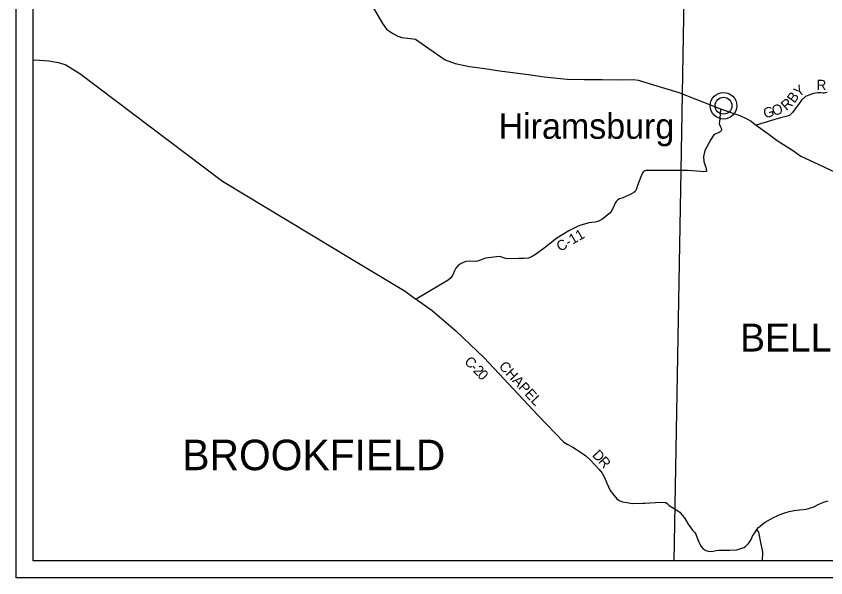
# Model space of a CAD drawing. Extents: x -452339 to 6403467, y -1 to 1814750.
# Drawn here: x -403540 to -379658, y 1603479 to 1620054 of the extents above; entities that cross this region are included whole.
import ezdxf

# ---------------------------------------------------------------- set-up
doc = ezdxf.new("R2010")
doc.units = 0
for name, color, linetype in [('Default', 7, 'Continuous'), ('GM_X_Adjacent_County_Text', 7, 'Continuous'), ('GM_X_County', 7, 'Continuous'), ('GM_X_County_Road', 7, 'Continuous'), ('GM_X_County_Road_Text', 7, 'Continuous'), ('GM_X_Section_Text', 7, 'Continuous'), ('GM_X_Township_Subdivision_Text', 7, 'Continuous')]:
    doc.layers.add(name, color=color, linetype=linetype)

msp = doc.modelspace()

# ---------------------------------------------------------------- linework, layer by layer
at = {"layer": 'Default'}
for p, q in [((-403040, 1603979), (-403040, 1661357)), ((-345663, 1603979), (-403040, 1603979))]:
    msp.add_line(p, q, dxfattribs=at)
msp.add_lwpolyline([(-403540, 1661857), (-345163, 1661857), (-345163, 1603479), (-403540, 1603479)], close=True, dxfattribs=at)
for points in [[(-403040, 1618761), (-402986, 1618762), (-402578, 1618733), (-402288, 1618691), (-402080, 1618619), (-401660, 1618363), (-397451, 1615188), (-393644, 1612887), (-392067, 1611935), (-391791, 1611737)], [(-379622, 1617798), (-379662, 1617791), (-379702, 1617783), (-379740, 1617784), (-379800, 1617793), (-379892, 1617795), (-380024, 1617775), (-380157, 1617728), (-380256, 1617681), (-380370, 1617576), (-380443, 1617481), (-380636, 1617211), (-380685, 1617158), (-380733, 1617127), (-380834, 1617093), (-380991, 1617054), (-381157, 1617007), (-381715, 1616841)], [(-382760, 1617316), (-382786, 1617034), (-382798, 1616944), (-382800, 1616892), (-382798, 1616861), (-382776, 1616813), (-382742, 1616749), (-382732, 1616703), (-382742, 1616675), (-382770, 1616643), (-382834, 1616607), (-382924, 1616573), (-382956, 1616555), (-382982, 1616525), (-383052, 1616412), (-383231, 1616087), (-383261, 1615913), (-383259, 1615770), (-383187, 1615558), (-383181, 1615475), (-383265, 1615460), (-383348, 1615469), (-383717, 1615497), (-384007, 1615505), (-384028, 1615504)], [(-384028, 1615504), (-384672, 1615496), (-384952, 1615500), (-384994, 1615490), (-385034, 1615466), (-385064, 1615428), (-385110, 1615311), (-385214, 1615055), (-385242, 1614961), (-385283, 1614884), (-385319, 1614846), (-385393, 1614816), (-385599, 1614718), (-385675, 1614687), (-385741, 1614661), (-385789, 1614631), (-385837, 1614587), (-385871, 1614535), (-385929, 1614397), (-385993, 1614292), (-386033, 1614242), (-386103, 1614178), (-386190, 1614110), (-386266, 1614056), (-386384, 1613997), (-386460, 1613971), (-386558, 1613961), (-386646, 1613953), (-386712, 1613937), (-386884, 1613888), (-386962, 1613860), (-387242, 1613722), (-387588, 1613501), (-387967, 1613206), (-388195, 1613037), (-388319, 1612961), (-388431, 1612913), (-388557, 1612901), (-388709, 1612900), (-389058, 1612890), (-389134, 1612910), (-389214, 1612946), (-389276, 1612960), (-389372, 1612949), (-389684, 1612913), (-389756, 1612893), (-389846, 1612857), (-389928, 1612826), (-390002, 1612814), (-390170, 1612820), (-390280, 1612814), (-390410, 1612758), (-390500, 1612695), (-390568, 1612617), (-390612, 1612539), (-390661, 1612423), (-390717, 1612337), (-390797, 1612266), (-391746, 1611704)], [(-391791, 1611737), (-391791, 1611737), (-391746, 1611704), (-391272, 1611365), (-390567, 1610765), (-389732, 1609970), (-388143, 1608271), (-387381, 1607484), (-387267, 1607410), (-387119, 1607336), (-387008, 1607266), (-386868, 1607170), (-386738, 1607080), (-386598, 1606956), (-386342, 1606678), (-386258, 1606564), (-386188, 1606436), (-386116, 1606270), (-386016, 1606054), (-385912, 1605920), (-385818, 1605814), (-385750, 1605760), (-385656, 1605718), (-385524, 1605700), (-385356, 1605674), (-385060, 1605679), (-385000, 1605682)], [(-385000, 1605682), (-384520, 1605708), (-384404, 1605706), (-384377, 1605704), (-384338, 1605674), (-384335, 1605671)], [(-384335, 1605671), (-384331, 1605667), (-384286, 1605620), (-384244, 1605597), (-384134, 1605524), (-383961, 1605414), (-383891, 1605329), (-383828, 1605252), (-383718, 1605066), (-383588, 1604888), (-383522, 1604818), (-383506, 1604784), (-383416, 1604560), (-383343, 1604410), (-383287, 1604342), (-383197, 1604288), (-383125, 1604264), (-383063, 1604258), (-382977, 1604268), (-382896, 1604287), (-382810, 1604297), (-382486, 1604299), (-382278, 1604305), (-382076, 1604374), (-382022, 1604404), (-381936, 1604488), (-381864, 1604608), (-381820, 1604707), (-381754, 1604811), (-381690, 1604909)], [(-381690, 1604909), (-381640, 1604967), (-381517, 1605069), (-381447, 1605122), (-381201, 1605260), (-381073, 1605322), (-380959, 1605367), (-380869, 1605401), (-380741, 1605437), (-380593, 1605465), (-380513, 1605473), (-380235, 1605510), (-380139, 1605530), (-380014, 1605572), (-379860, 1605649), (-379766, 1605695), (-379722, 1605711), (-379586, 1605749)], [(-381521, 1603979), (-381516, 1604223), (-381524, 1604291), (-381560, 1604475), (-381638, 1604829), (-381658, 1604867), (-381690, 1604909)]]:
    msp.add_lwpolyline(points, dxfattribs=at)
at = {"layer": 'GM_X_County_Road'}
msp.add_lwpolyline([(-393477, 1621106), (-392730, 1619837), (-392615, 1619675), (-392530, 1619609), (-392432, 1619547), (-392265, 1619452), (-392247, 1619451), (-392165, 1619427), (-391992, 1619405), (-391764, 1619379), (-391371, 1619098), (-390890, 1618764), (-390593, 1618659), (-390170, 1618573), (-389719, 1618515), (-389280, 1618443), (-388428, 1618336), (-387965, 1618264), (-387286, 1618195), (-386781, 1618186), (-386250, 1618188), (-385687, 1618179), (-385330, 1618183), (-385186, 1618167), (-385062, 1618130), (-383990, 1617804), (-382760, 1617316), (-382398, 1617192), (-382197, 1617125), (-382008, 1617034), (-381858, 1616954), (-381737, 1616856), (-381715, 1616841), (-381366, 1616595), (-381090, 1616386), (-380614, 1616078), (-380391, 1615926), (-379863, 1615680), (-379083, 1615313)], dxfattribs=at)
at = {"layer": 'GM_X_County_Road_Text'}
for radius in [393, 249]:
    msp.add_circle((-382675, 1617412), radius, dxfattribs=at)
at = {"layer": 'GM_X_Section_Text'}
for p, q in [((-383695, 1628810), (-383932, 1615503)), ((-383932, 1615503), (-384137, 1603979))]:
    msp.add_line(p, q, dxfattribs=at)

# ---------------------------------------------------------------- texts
at = {"layer": 'GM_X_Adjacent_County_Text'}
for s, height, p in [('Hiramsburg', 750, (-389311, 1616436)), ('BELLE VALLEY', 823.68, (-382185, 1610157))]:
    msp.add_text(s, height=height, rotation=0, dxfattribs=at).set_placement(p)
at = {"layer": 'GM_X_County'}
for s, rotation, p in [('Y', 37.7945, (-380456, 1617651)), ('R', 0.1836, (-379932, 1617876)), ('B', 54.1603, (-380585, 1617467)), ('R', 41.3104, (-380819, 1617250)), ('G', 15.9564, (-381453, 1617036)), ('O', 16.0094, (-381199, 1617109)), ('C-11', 30.0336, (-387496, 1613097)), ('C', 315.8418, (-390342, 1609833)), ('-', 314.9117, (-390167, 1609662)), ('2', 314.2567, (-390080, 1609576)), ('CHAPEL', 312.9989, (-389320, 1609705)), ('0', 313.7672, (-389952, 1609444)), ('D', 313.0162, (-386566, 1607087)), ('R', 312.2225, (-386387, 1606895))]:
    msp.add_text(s, height=300, rotation=rotation, dxfattribs=at).set_placement(p)
at = {"layer": 'GM_X_Township_Subdivision_Text'}
msp.add_text('BROOKFIELD', height=900, rotation=0, dxfattribs=at).set_placement((-398640, 1606656))

doc.saveas('drawing.dxf')
